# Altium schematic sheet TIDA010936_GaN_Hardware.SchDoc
size 431 x 279 mm; Date: Not shown in title block; ApprovedBy: Not shown in title block; CheckedBy: Not shown in title block; Author: Not shown in title block; CompanyName: Not shown in title block; DrawnBy: e; Engineer: Not shown in title block; Organization: Not shown in title block; Address1: Not shown in title block; Address2: Not shown in title block; Address3: Not shown in title block; Address4: Not shown in title block; DocumentNumber: 3; Revision: Use project parameter SCH_Rev; SheetNumber: 2; SheetTotal: 2; PageSetup: Record=PageOptions¦CenterHorizontal=True¦CenterVertical=True¦PrintScale=1.00¦XCorrection=1.00¦YCorrection=1.00¦PrintKind=0¦BorderSize=5000000¦LeftOffset=0¦BottomOffset=0¦Orientation=2¦PaperLength=1000¦PaperWidth=1000¦Scale=100¦PaperSource=15¦PrintQuality=600¦MediaType=1¦DitherType=10¦PaperKind=Letter¦PrintScaleMode=1
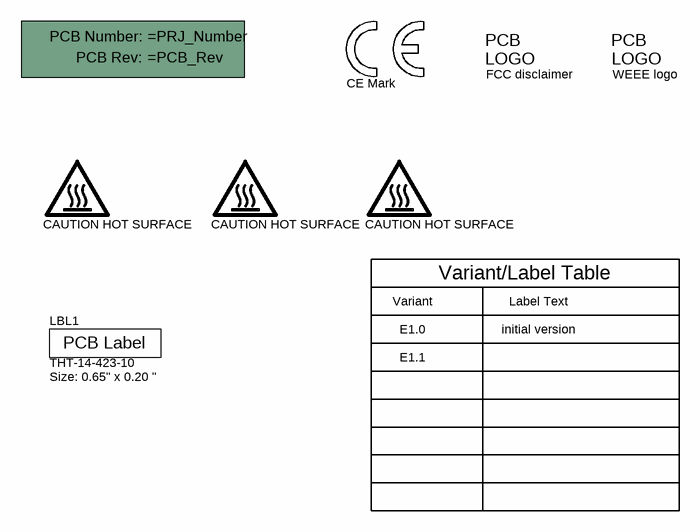
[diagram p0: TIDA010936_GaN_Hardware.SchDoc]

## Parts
2  CE Mark  [CE_Mark_5mm]  (no BOM)
4  FCC disclaimer  [FCC_disclaimer]  (no BOM)
5  WEEE logo  [WEEE_Minimum]  (no BOM)
6  CAUTION HOT SURFACE  [IEC_HotSurface_Small]  (no BOM)
7  CAUTION HOT SURFACE  [IEC_HotSurface_Small]  (no BOM)
8  CAUTION HOT SURFACE  [IEC_HotSurface_Small]  (no BOM)
!PCB1  Printed Circuit Board  (value not drawn)  (mechanical)
LBL1  THT-14-423-10  Note: Size: 0.65" x 0.20 "  [Label_650x200]

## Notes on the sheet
- Variant
- Variant/Label Table
- Label Text
- E1.0
- E1.1
- initial version

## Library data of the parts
2 = CMP-0074844-1: SymbolCreator: a0412235
4 = CMP-0074847-1: FCC_disclaimer; Library Reference: Logo
5 = CMP-0074769-3: Manufacturer: Texas Instruments; CompType: IC; AEC Category: Q200
6-8 = CMP-0074837-1: IEC 61010-1 Hot Surface Warning; SymbolCreator: a0412235
!PCB1 = CMP-0003618-2: Manufacturer: Any
LBL1 = CMP-0003625-1: Thermal Transfer Printable Labels, 0.650" W x 0.200" H - 10,000 per roll; Manufacturer: Brady; CompType: Label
